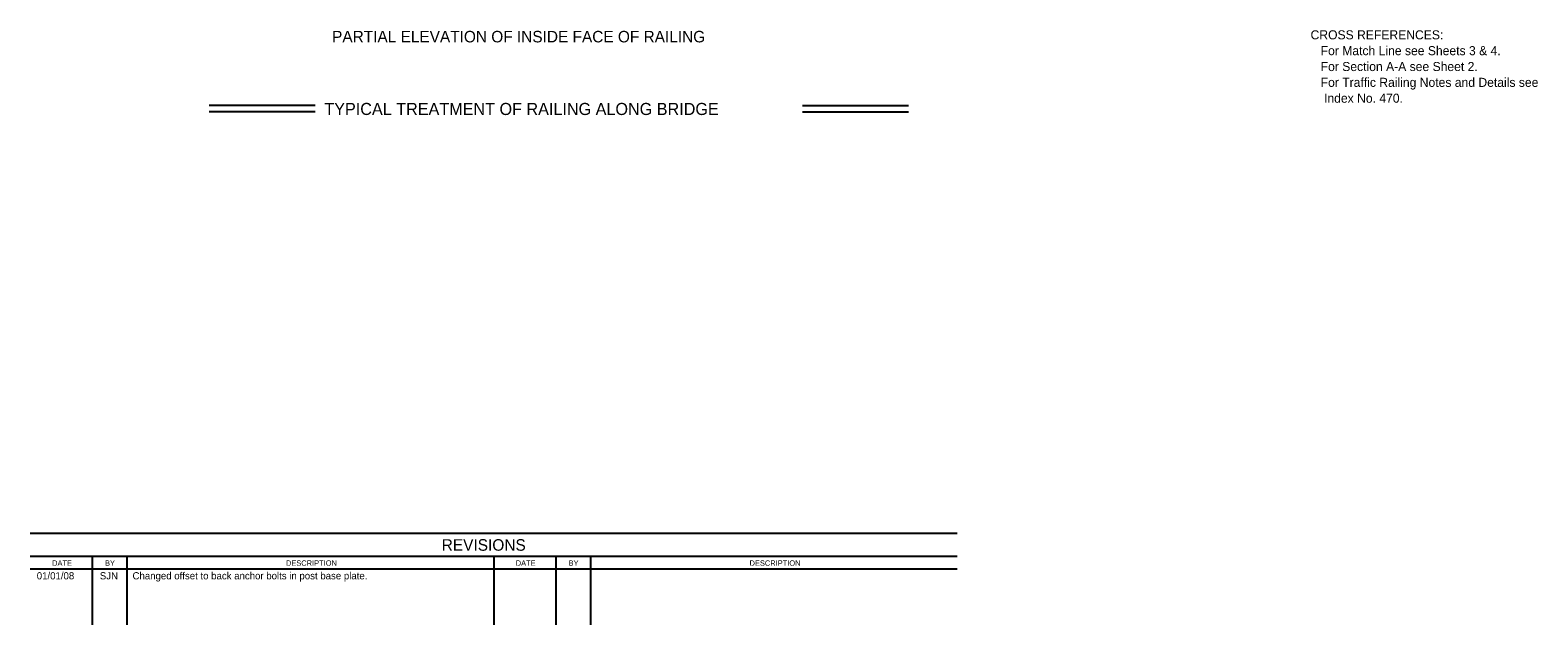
# Model space of a CAD drawing. Extents: x 21629.5 to 21698.8, y 56199.1 to 56237.6.
# Drawn here: x 21629.5 to 21663.02, y 56199.09 to 56212.3 of the extents above; entities that cross this region are included whole.
import ezdxf

# ---------------------------------------------------------------- set-up
doc = ezdxf.new("R2010")
doc.units = 0
for name, color, linetype in [('Border', 7, 'Continuous'), ('Dimension', 7, 'Continuous'), ('TextStructures', 7, 'Continuous')]:
    doc.layers.add(name, color=color, linetype=linetype)

msp = doc.modelspace()

# ---------------------------------------------------------------- linework, layer by layer
at = {"layer": 'Border'}
for p, q in [((21650.111, 56201.115), (21629.499, 56201.115)), ((21650.111, 56200.6), (21629.499, 56200.6)), ((21629.499, 56200.327), (21650.111, 56200.327)), ((21630.876, 56200.6), (21630.876, 56199.085)), ((21631.649, 56200.6), (21631.649, 56199.085)), ((21639.805, 56200.6), (21639.805, 56199.085)), ((21641.182, 56200.6), (21641.182, 56199.085)), ((21641.955, 56200.6), (21641.955, 56199.085))]:
    msp.add_line(p, q, dxfattribs=at)
at = {"layer": 'Dimension'}
for p, q in [((21635.838, 56210.624), (21633.476, 56210.624)), ((21635.838, 56210.483), (21633.476, 56210.483)), ((21646.666, 56210.624), (21649.028, 56210.624)), ((21646.666, 56210.483), (21649.028, 56210.483))]:
    msp.add_line(p, q, dxfattribs=at)

# ---------------------------------------------------------------- texts
for s, p in [('CROSS REFERENCES:', (21657.964, 56212.095)), ('   For Match Line see Sheets 3 & 4.', (21657.964, 56211.743)), ('   For Section A-A see Sheet 2.', (21657.964, 56211.391)), ('   For Traffic Railing Notes and Details see ', (21657.964, 56211.039)), ('    Index No. 470.', (21657.964, 56210.687))]:
    msp.add_text(s, height=0.2016, dxfattribs=at).set_placement(p)
at = {"layer": 'TextStructures'}
for s, height, p in [('PARTIAL ELEVATION OF INSIDE FACE OF RAILING', 0.256, (21636.212, 56212.028)), ('TYPICAL TREATMENT OF RAILING ALONG BRIDGE', 0.2688, (21636.039, 56210.414)), ('REVISIONS', 0.2567, (21638.648, 56200.732)), ('BY', 0.1201, (21631.163, 56200.398)), ('BY', 0.1201, (21641.469, 56200.398)), ('01/01/08', 0.16, (21629.646, 56200.095)), ('SJN', 0.16, (21631.048, 56200.095)), ('Changed offset to back anchor bolts in post base plate.', 0.16, (21631.775, 56200.095))]:
    msp.add_text(s, height=height, dxfattribs=at).set_placement(p)
for s, height, rotation, p in [('DATE', 0.1196, 359.8693, (21629.988, 56200.398)), ('DESCRIPTION', 0.12007, 0.0498, (21635.186, 56200.397)), ('DATE', 0.1196, 359.8693, (21640.294, 56200.398)), ('DESCRIPTION', 0.12007, 0.0498, (21645.492, 56200.397))]:
    msp.add_text(s, height=height, rotation=rotation, dxfattribs=at).set_placement(p)

doc.saveas('drawing.dxf')
